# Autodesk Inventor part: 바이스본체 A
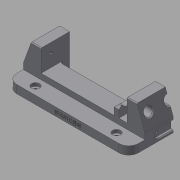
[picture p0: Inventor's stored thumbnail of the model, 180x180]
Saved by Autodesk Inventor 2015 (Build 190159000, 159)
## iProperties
Created: 2017-04
Part Number: 바이스본체 A
Material: 일반
Document SubType Name: Modeling
Designer: mduedu
Density: 1 g/cm^3
Appearance: 기본값
Author: mduedu
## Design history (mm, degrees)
sketch "스케치1"
  geometry: L1 (-75, 0)-(75, 0); L2 (-75, 0)-(-75, 17); L3 (-53, 17)-(53, 17); L4 (75, 17)-(75, 0); L5 (-75, 17)-(-65.173, 44); L6 (-65.173, 44)-(-53, 44); L7 (-53, 44)-(-53, 17); L8 (0, 0)-(0, 17); L9 (75, 17)-(65.173, 44); L10 (65.173, 44)-(53, 44); L11 (53, 44)-(53, 17); 1 further point
  constraints: 22 end point, 4 perpendicular, 2 horizontal alignment, 2 midpoint, 2 symmetric about line, 1 coincident, 1 collinear, 1 horizontal, 1 vertical
  dimensions: "d0" = 150 distance of L1.start L1.end; "d1" = 17 distance of L1.start L2.end; "d2" = 27 distance of L3.start L6.end; "d3" = 22 distance of L3.start L2.end; "d4" = 70 deg angle of L3 L5; "d54" = 20 deg angle of L9 L4
extrude "돌출1" new body sketch "스케치1" stored distance "d5" = 70; taper "d6" = 0 deg
sketch "스케치2"
  geometry: L1 (0, 70)-(106, 70) reference; L2 (106, 70)-(106, 0) reference; L3 (106, 0)-(0, 0) reference; L4 (0, 47)-(106, 47); L5 (106, 47)-(106, 23); L6 (106, 23)-(0, 23); L7 (0, 23)-(0, 47); L8 (0, 70)-(0, 0) reference; 2 further points
  constraints: 8 end point, 2 parallel, 2 point on line, 1 horizontal, 1 horizontal alignment, 1 midpoint, 1 perpendicular
  dimensions: "d7" = 24 distance between parallel lines of L6 L4
extrude "돌출2" cut sketch "스케치2" stored distance "d9" = 70; taper "d10" = 0 deg
sketch "스케치3"
  geometry: L1 (22, -23)-(128, -23) reference; L2 (128, -47)-(22, -47) reference; L3 (22, -18)-(128, -18); L4 (128, -52)-(22, -52); L5 (22, -18)-(22, -52); L6 (128, -18)-(128, -52); 1 further point
  constraints: 8 end point, 3 parallel, 2 point on line, 1 perpendicular
  dimensions: "d11" = 5 distance between parallel lines of L3 L1; "d12" = 5 distance between parallel lines of L4 L2
extrude "돌출3" cut sketch "스케치3" distance "d13" = 12; taper "d14" = 0 deg
fillet "모깎기1" dims "d15" = 3, "d16" = 3
sketch "스케치4"
  geometry: L1 (103, 23)-(3, 23) reference; L2 (0, 26)-(0, 0) reference; L3 (106, 0)-(0, 0) reference; L4 (106, 26)-(106, 0) reference; L5 (96, 0)-(90, 0); L6 (90, 0)-(90, 19.5); L7 (96, 19.5)-(96, 0); L8 (90, 19.5)-(96, 19.5); A1 r 3 centre (3, 26) between (0, 26) and (3, 23) reference; A2 r 3 centre (103, 26) between (103, 23) and (106, 26) reference; 1 further point
  constraints: 8 end point, 2 perpendicular, 1 horizontal, 1 parallel, 1 point on line
  dimensions: "d17" = 10 distance between parallel lines of L7 L4; "d18" = 6 distance between parallel lines of L7 L6; "d27" = 3.5 distance between parallel lines of L8 L1
extrude "돌출4" join sketch "스케치4" distance "d19" = 12; taper "d20" = 0 deg
chamfer "모따기1" distance "d21" = 3; stored, may be unused: second distance "d22" = 2, angle "d23" = 45 deg
chamfer "모따기2" distance "d24" = 3; stored, may be unused: second distance "d25" = 2, angle "d26" = 45 deg
sketch "스케치5"
  geometry: L1 (-15.5, 35.8)-(-15.5, -25.8) reference; L2 (19.5, 0)-(0, 0) reference; C1 r 6.5 at (9.5, 15); 1 further point
  constraints: 1 centre point
  dimensions: "d28" = 13 diameter of C1; "d30" = 15 distance from line of C1.centre L2; "d31" = 25 distance from line of C1.centre L1
extrude "돌출5" cut sketch "스케치5" stored distance "d32" = 12; taper "d33" = 0 deg
sketch "스케치6"
  geometry: C1 r 5 at (-10, 15); C2 r 5 at (-60, 15); A1 r 6.5 centre (-10, 15) between (-15.766, 12) and (-4.234, 12) reference; A2 r 6.5 centre (-60, 15) between (-65.766, 12) and (-54.234, 12) reference; 1 further point
  constraints: 2 centre point, 2 coincident
  dimensions: "d34" = 10 diameter of C1; "d35" = 10 diameter of C2 (= d34)
extrude "돌출6" cut sketch "스케치6" stored distance "d36" = 12; taper "d37" = 0 deg
chamfer "모따기3" distance "d38" = 1; stored, may be unused: second distance "d39" = 2, angle "d40" = 45 deg
chamfer "모따기4" distance "d41" = 1; stored, may be unused: second distance "d42" = 2, angle "d43" = 45 deg
sketch "스케치7"
  geometry: L1 (-35, 35.8)-(-35, -25.8) reference; L2 (-70, 0)-(0, 0) reference; C1 r 5 at (-35, 15); 1 further point
  constraints: 1 centre point, 1 point on line
  dimensions: "d44" = 10 diameter of C1; "d45" = 15 distance from line of C1.centre L2
extrude "돌출7" cut sketch "스케치7" stored distance "d46" = 12; taper "d47" = 0 deg
chamfer "모따기5" distance "d48" = 1; stored, may be unused: second distance "d49" = 2, angle "d50" = 45 deg
node "작업축1"
sketch "스케치8"
  geometry: L1 (-105, 32)-(105, 32) reference; L2 (58, 32)-(64, 32); L3 (64, 32)-(64, 40); L4 (64, 40)-(58, 40); L5 (58, 40)-(58, 32); L6 (53, 38)-(53, 26) reference; 1 further point
  constraints: 8 end point, 2 parallel, 1 horizontal, 1 perpendicular, 1 point on line
  dimensions: "d51" = 5 distance from line of L6 L2.start; "d52" = 6 distance of L3.end L4.end; "d53" = 16 diameter of L4 L1
revolve "회전1" sketch "스케치8" stored, may be unused: angle "d55" = 90 deg
fillet "모깎기2"
chamfer "모따기6" distance "d56" = 1; stored, may be unused: second distance "d57" = 2, angle "d58" = 45 deg
sketch "스케치9"
  geometry: L1 (17.5, 3)-(52.5, 3); L2 (52.5, 13)-(17.5, 13); L3 (70, 0)-(0, 0) reference; L4 (17.5, 8)-(52.5, 8); A1 r 5 centre (17.5, 8) between (17.5, 13) and (17.5, 3); A2 r 5 centre (52.5, 8) between (52.5, 3) and (52.5, 13); 3 further points
  constraints: 6 end point, 4 point on circle, 3 tangent, 2 centre point, 2 midpoint, 2 parallel, 1 horizontal, 1 vertical alignment
  dimensions: "d59" = 35 distance of L4.start L4.end; "d61" = 5 radius of A2; "d62" = 8 distance between parallel lines of L3 L4
extrude "돌출8" cut sketch "스케치9" distance "d63" = 3; taper "d64" = 0 deg
chamfer "모따기7" distance "d65" = 1; stored, may be unused: second distance "d66" = 2, angle "d67" = 45 deg
chamfer "모따기8" distance "d68" = 1; stored, may be unused: second distance "d69" = 2, angle "d70" = 45 deg
feature "분할1"
sketch "스케치10"
  geometry: L1 (35, 27)-(0, 27) reference; L2 (0, 0)-(0, 27) reference; 1 further point
  dimensions: "d85" = 11.5 distance from line of point (12, 15.5) L1; "d86" = 12 distance from line of point (12, 15.5) L2
hole "구멍1" sketch "스케치10" at (12, 15.5) diameter "d71" = 3.242; stored, may be unused: countersink angle "d75" = 90 deg, drill point angle "d77" = 120 deg; dims "d72" = 6, "d73" = 4, "d74" = 2, "d76" = 8
sketch "스케치11"
  geometry: A1 r 5 centre (17.5, 8) between (17.5, 13) and (17.5, 3) reference; 1 further point
  constraints: 1 coincident
hole "구멍3" sketch "스케치11" at (17.5, 8) diameter "d78" = 2.459; stored, may be unused: countersink angle "d82" = 90 deg, drill point angle "d84" = 120 deg; dims "d79" = 4.5, "d80" = 4, "d81" = 2, "d83" = 6
sketch "스케치13"
  geometry: L1 (75, 0)-(75, 35) reference; L2 (-75, 0)-(-75, 35) reference; L3 (-75, 35)-(75, 35); L4 (75, 35)-(75, 55); L5 (75, 55)-(-75, 55); L6 (-75, 55)-(-75, 35); 1 further point
  constraints: 8 end point, 2 parallel, 1 horizontal, 1 perpendicular, 1 point on line
  dimensions: "d90" = 20 distance between parallel lines of L5 L3; "d94" = 150 distance of L4.end L5.end (derived)
extrude "돌출9" join sketch "스케치13" distance "d92" = 10; taper "d93" = 0 deg
sketch "스케치14"
  geometry: L1 (-75, -35)-(-75, -55) reference; L2 (75, -55)-(75, -35) reference; L3 (-75, -45)-(75, -45); 3 further points
  constraints: 2 end point, 2 midpoint, 2 point on line
  dimensions: "d95" = 50 horizontal distance of point (-50, -45) point (0, 0); "d96" = 100 distance of point (50, -45) point (-50, -45)
fillet "모깎기3" dims "d97" = 12
chamfer "모따기9" distance "d98" = 1; stored, may be unused: second distance "d99" = 2, angle "d100" = 45 deg
hole "구멍4" sketch "스케치14" diameter "d101" = 4.134; stored, may be unused: countersink angle "d105" = 90 deg, drill point angle "d107" = 118 deg; dims "d102" = 6, "d103" = 10, "d104" = 4, "d106" = 8
sketch "스케치15"
  geometry: L1 (0, 0)-(126, 0) reference; 3 further points
  constraints: 1 midpoint, 1 vertical alignment, 1 other
  dimensions: "d109" = 5 distance from line of point (63, 5) L1
feature "엠보싱2" sketch "스케치15" dims "d0" = 150, "d1" = 17, "d2" = 27, "d3" = 22, "d4" = 70 deg, "d54" = 20 deg, "d110" = 0.5, "d111" = 0
node "솔리드1"
mirror "대칭1"
mirror "대칭2"
mirror "대칭3"
mirror "대칭4"
node "투영된 루프1"
